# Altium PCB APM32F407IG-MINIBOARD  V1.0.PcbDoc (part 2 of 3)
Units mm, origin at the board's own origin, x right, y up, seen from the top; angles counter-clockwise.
Board outline 442.79 x 366.46 mm, 2 copper layers (Top Layer, Bottom Layer); 220 components, 190 nets, 1232 pads, 648 vias.
Unrouted connection lines stored in the file: 190.
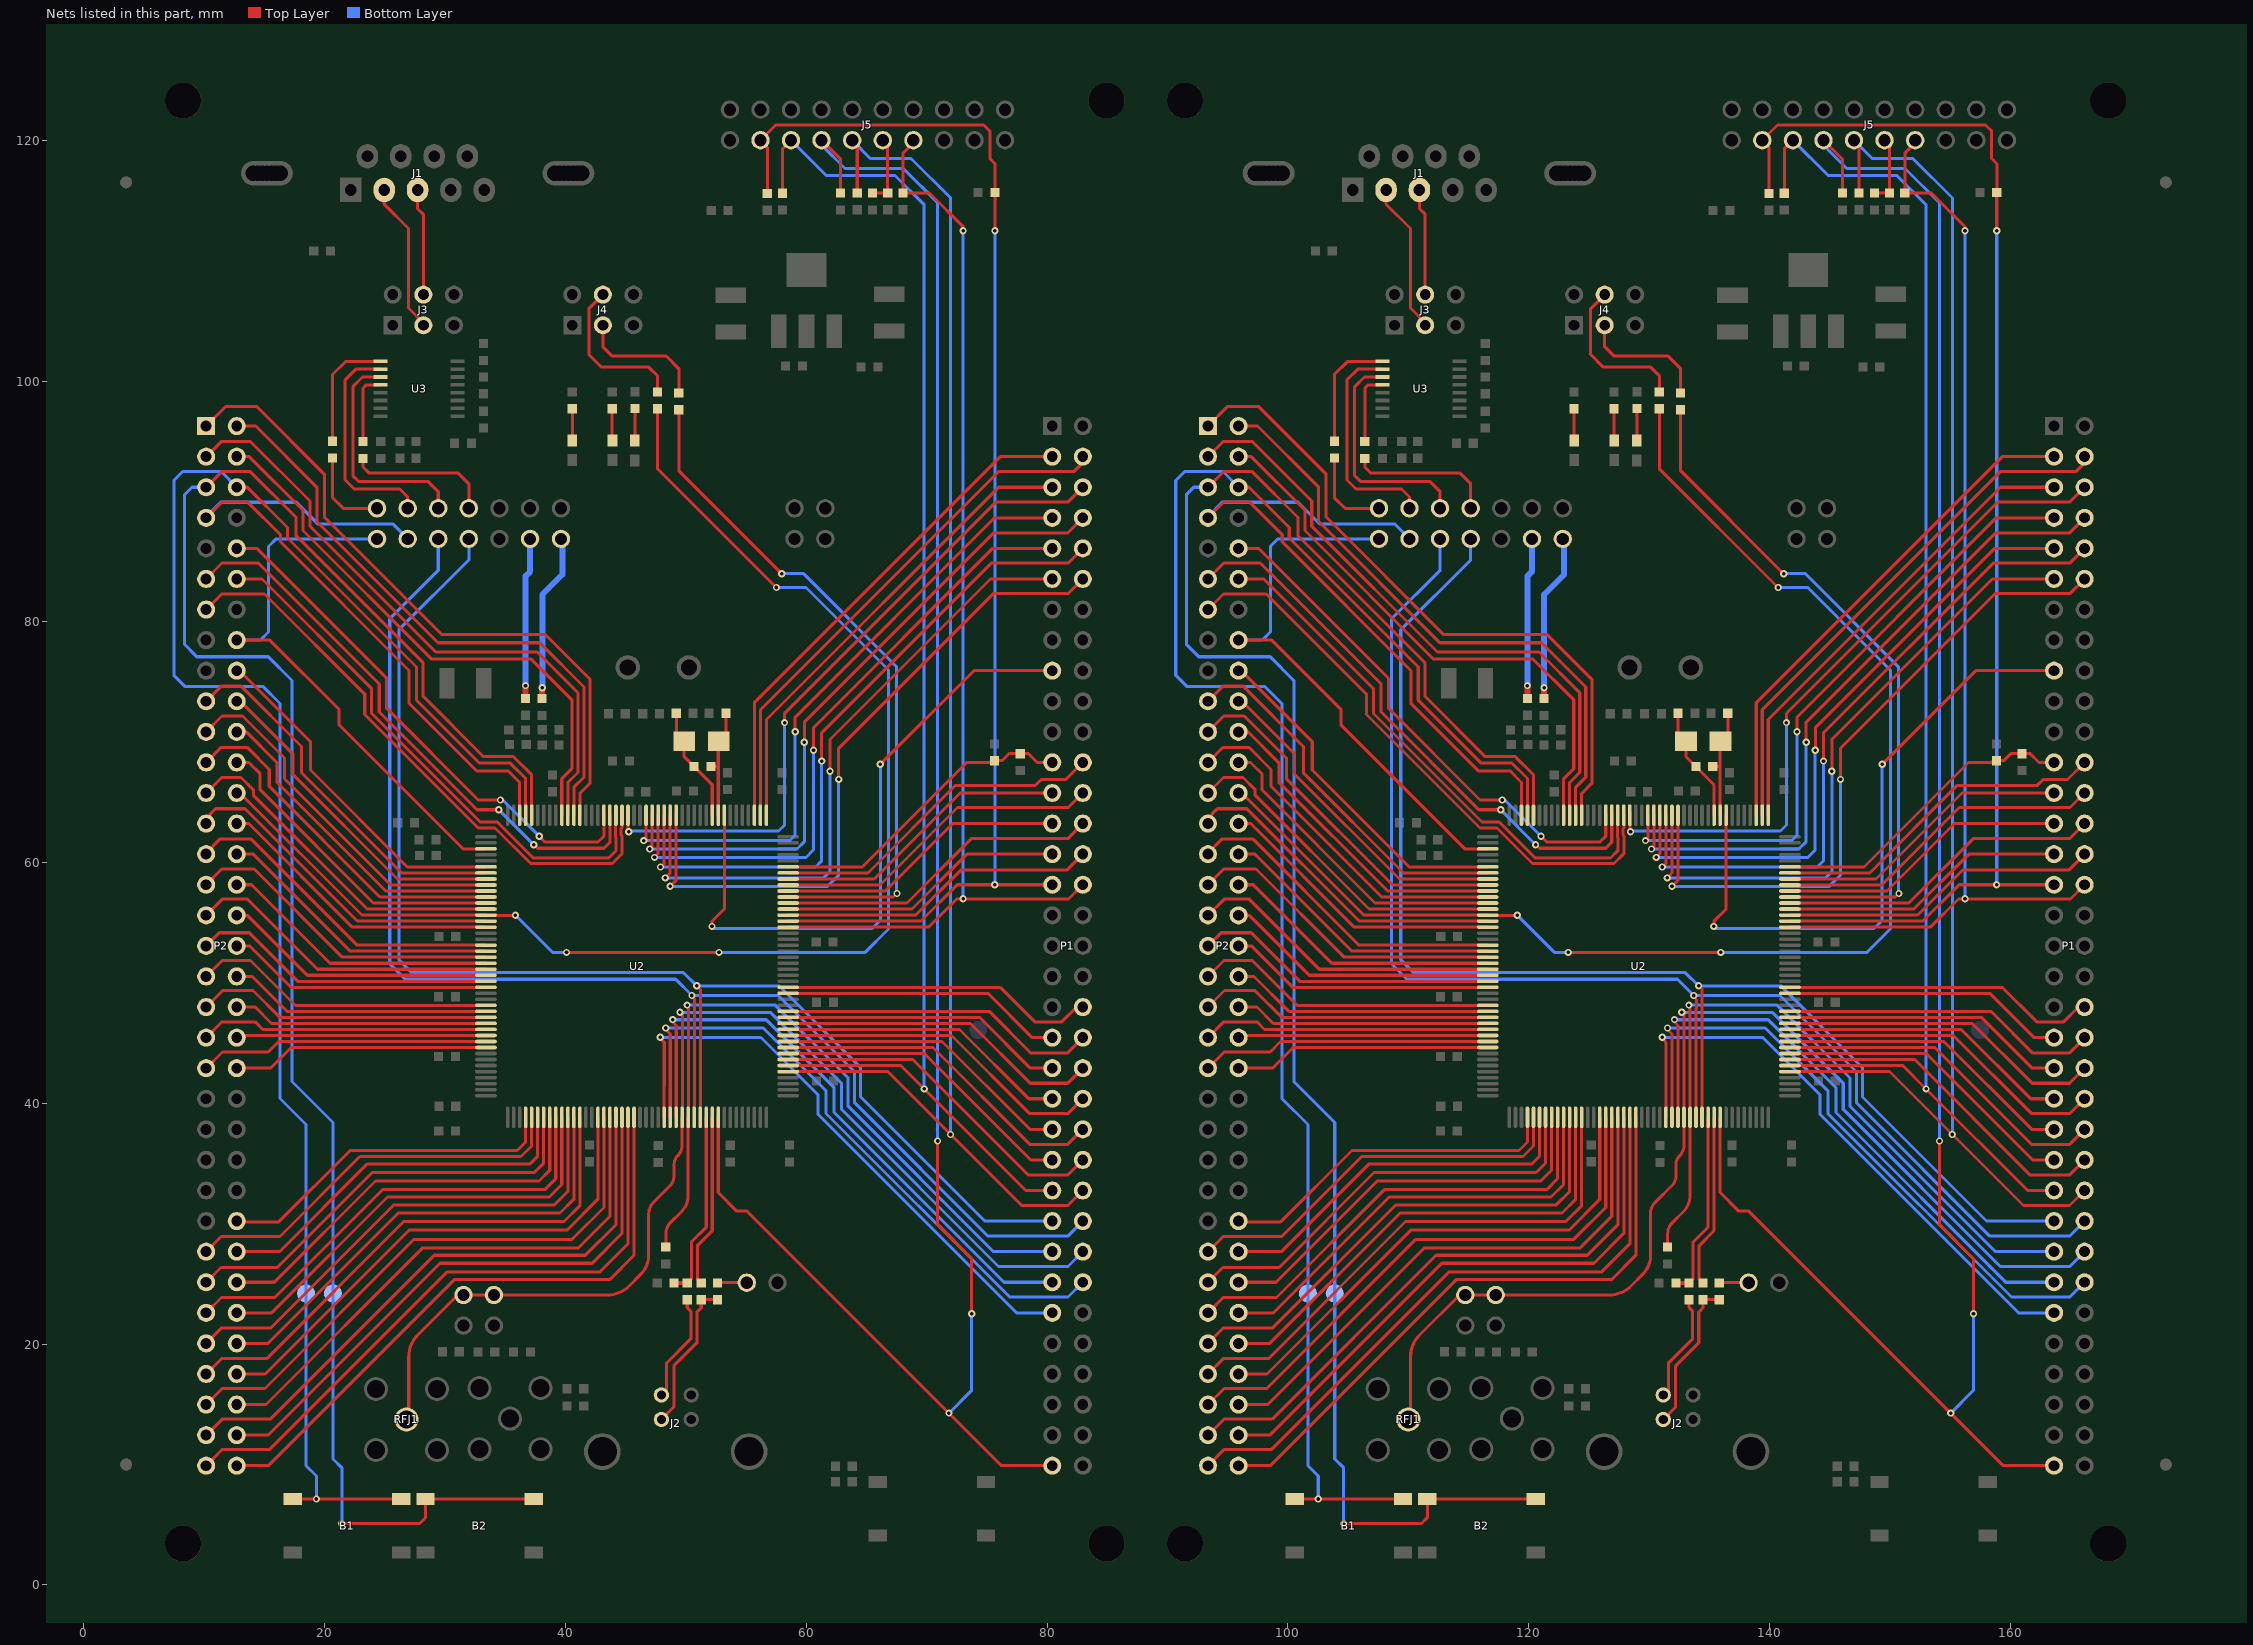
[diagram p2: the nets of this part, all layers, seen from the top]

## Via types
v1: diameter 0.6, hole 0.3, Top Layer to Bottom Layer, 648 vias

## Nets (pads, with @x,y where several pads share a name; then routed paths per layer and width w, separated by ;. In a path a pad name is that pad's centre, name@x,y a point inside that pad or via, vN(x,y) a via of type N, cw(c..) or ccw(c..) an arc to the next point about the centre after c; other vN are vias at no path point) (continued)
NetJ2_2: J2.2 R2.1 | length 18.1
  Top Layer w0.254: J2.2@47.962,15.774 48.39,16.202 48.39,18.412 50.414,20.436 50.414,22.724 50.114,23.024 R2.1@50.114,23.689 ; J2.2@131.182,15.774 131.61,16.202 131.61,18.412 133.634,20.436 133.634,22.724 133.334,23.024 R2.1@133.334,23.689
NetJ2_3: J2.3 R1.1 R4.1 | length 25.3
  Top Layer w0.254: J2.3@47.962,13.742 49,14.78 49,18.192 50.914,20.106 50.914,22.656 51.273,23.015 R1.1@51.273,23.689 R4.1@52.614,23.689 ; J2.3@131.182,13.742 132.22,14.78 132.22,18.192 134.134,20.106 134.134,22.656 134.493,23.015 R1.1@134.493,23.689 R4.1@135.834,23.689
NetJ4_3: J4.3 R6.2 | length 21.8
  Top Layer w0.254: J4.3@43.103,104.637 43.103,102.837 43.85,102.09 48.35,102.09 49.41,101.03 R6.2@49.41,99.007 ; J4.3@126.323,104.637 126.323,102.837 127.07,102.09 131.57,102.09 132.63,101.03 R6.2@132.63,99.007
NetJ4_4: J4.4 R8.1 | length 26.5
  Top Layer w0.254: J4.4@43.103,107.177 41.94,106.014 41.94,102.2 42.99,101.15 46.92,101.15 47.64,100.43 R8.1@47.64,99.095 ; J4.4@126.323,107.177 125.16,106.014 125.16,102.2 126.21,101.15 130.14,101.15 130.86,100.43 R8.1@130.86,99.095
NetJ5_11: J5.11 R24.2 R25.1 | length 11.6
  Top Layer w0.254: R24.2@65.514,115.613 65.524,115.623 R25.1@66.764,115.623 66.764,119.595 J5.11@66.354,120.005 ; R24.2@148.734,115.613 148.744,115.623 R25.1@149.984,115.623 149.984,119.595 J5.11@149.574,120.005
NetJ7_2: J7.2 L2.2 | length 28.2
  Top Layer w0.5: L2.2@38.06,73.627 38.06,74.52 v1(38.07,74.53) ; L2.2@121.28,73.627 121.28,74.52 v1(121.29,74.53)
  Bottom Layer w0.5: v1(38.07,74.53) 38.07,82.27 39.73,83.93 39.73,86.78 J7.2@39.62,86.89 ; J7.2@39.13,86.89 J7.2@39.13,86.97 ; v1(121.29,74.53) 121.29,82.27 122.95,83.93 122.95,86.78 J7.2@122.84,86.89 ; J7.2@122.35,86.89 J7.2@122.35,86.97
NetJ8_2: J8.2 L1.2 | length 26.8
  Top Layer w0.5: v1(36.68,74.7) 36.688,74.692 L1.2@36.688,73.637 ; v1(119.9,74.7) 119.908,74.692 L1.2@119.908,73.637
  Bottom Layer w0.5: v1(36.68,74.7) 36.68,83.79 37.06,84.17 J8.2@37.06,86.89 ; v1(119.9,74.7) 119.9,83.79 120.28,84.17 J8.2@120.28,86.89
NetJ10_2: J10.2 R4.2 | length 4.9
  Top Layer w0.254: R4.2@52.614,25.086 R4.2@52.62,25.08 ; R4.2@52.614,25.105 J10.2@55.06,25.105 ; R4.2@135.834,25.086 R4.2@135.84,25.08 ; R4.2@135.834,25.105 J10.2@138.28,25.105
NetJ11_1: J11.1 U3.11 | length 38.1
  Top Layer w0.254: U3.11@24.635,100.334 23.144,100.334 22.33,99.52 22.33,92.14 22.8,91.67 28.56,91.67 29.43,90.8 J11.1@29.43,89.43 ; U3.11@107.855,100.334 106.364,100.334 105.55,99.52 105.55,92.14 106.02,91.67 111.78,91.67 112.65,90.8 J11.1@112.65,89.43
NetJ12_1: J12.1 R27.1 | length 24.2
  Top Layer w0.254: R27.1@23.174,93.576 23.174,92.855 23.65,92.38 31.05,92.38 31.97,91.46 J12.1@31.97,89.43 ; R27.1@106.394,93.576 106.394,92.855 106.87,92.38 114.27,92.38 115.19,91.46 J12.1@115.19,89.43
NetJ13_1: J13.1 U3.10 | length 36.7
  Top Layer w0.254: U3.10@24.635,100.984 22.584,100.984 21.7,100.1 21.7,91.78 22.44,91.04 26.22,91.04 26.89,90.37 J13.1@26.89,89.43 ; U3.10@107.855,100.984 105.804,100.984 104.92,100.1 104.92,91.78 105.66,91.04 109.44,91.04 110.11,90.37 J13.1@110.11,89.43
NetJ14_1: J14.1 R28.1 | length 14.7
  Top Layer w0.254: R28.1@20.65,93.601 20.65,90.31 21.53,89.43 J14.1@24.35,89.43 ; R28.1@103.87,93.601 103.87,90.31 104.75,89.43 J14.1@107.57,89.43
NetLED1_1: LED1.1 R7.1 | length 5.2
  Top Layer w0.254: LED1.1@40.563,95.073 R7.1@40.563,97.698 ; LED1.1@123.783,95.073 R7.1@123.783,97.698
NetLED2_1: LED2.1 R12.2 | length 5.3
  Top Layer w0.254: R12.2@43.877,97.703 43.877,95.091 LED2.1@43.907,95.061 ; R12.2@127.097,97.703 127.097,95.091 LED2.1@127.127,95.061
NetLED3_1: LED3.1 R11.2 | length 5.6
  Top Layer w0.254: LED3.1@45.76,94.901 45.78,94.921 R11.2@45.78,97.713 ; LED3.1@128.98,94.901 129,94.921 R11.2@129,97.713
NetR6_1: R6.1 U2.166 | length 115.9
  Top Layer w0.254: R6.1@49.41,97.61 49.41,92.55 57.96,84 v1(57.97,84) ; U2.166@58.49,57.14 67.25,57.14 v1(67.54,57.43) ; R6.1@132.63,97.61 132.63,92.55 141.18,84 v1(141.19,84) ; U2.166@141.71,57.14 150.47,57.14 v1(150.76,57.43)
  Bottom Layer w0.254: v1(57.97,84) 59.78,84 67.5,76.28 67.5,57.47 v1(67.54,57.43) ; v1(141.19,84) 143,84 150.72,76.28 150.72,57.47 v1(150.76,57.43)
NetR27_2: R27.2 U3.12 | length 12
  Top Layer w0.254: R27.2@23.174,94.973 23.174,99.414 23.444,99.684 U3.12@24.635,99.684 ; R27.2@106.394,94.973 106.394,99.414 106.664,99.684 U3.12@107.855,99.684
NetR28_2: R28.2 U3.9 | length 20
  Top Layer w0.254: R28.2@20.65,94.998 20.65,100.54 21.72,101.611 24.612,101.611 U3.9@24.635,101.634 U3.9@24.658,101.611 ; R28.2@103.87,94.998 103.87,100.54 104.94,101.611 107.832,101.611 U3.9@107.855,101.634 U3.9@107.878,101.611
PA0: B2.2 B2.3 P2.5 TP5.1 U2.40 | length 316
  Top Layer w0.254: P2.5@10.15,91.181 11.439,92.47 13.82,92.47 17.63,88.66 17.63,87.14 28.17,76.6 28.17,73.81 33.18,68.8 35.676,68.8 37.19,67.286 U2.40@37.19,63.94 ; v1(21.42,5.098) 27.88,5.098 28.37,5.588 B2.2@28.37,7.145 B2.3@37.37,7.145 ; P2.5@93.37,91.181 94.659,92.47 97.04,92.47 100.85,88.66 100.85,87.14 111.39,76.6 111.39,73.81 116.4,68.8 118.896,68.8 120.41,67.286 U2.40@120.41,63.94 ; v1(104.64,5.098) 111.1,5.098 111.59,5.588 B2.2@111.59,7.145 B2.3@120.59,7.145
  Bottom Layer w0.254: P2.5@10.15,91.181 8.971,91.181 8.35,90.56 8.35,78.13 9.38,77.1 15.31,77.1 17.28,75.13 17.28,41.81 20.68,38.41 TP5.1@20.68,24.21 20.68,10.458 21.42,9.718 v1(21.42,5.098) ; P2.5@93.37,91.181 92.191,91.181 91.57,90.56 91.57,78.13 92.6,77.1 98.53,77.1 100.5,75.13 100.5,41.81 103.9,38.41 TP5.1@103.9,24.21 103.9,10.458 104.64,9.718 v1(104.64,5.098)
PA1: B1.2 B1.3 P2.6 TP6.1 U2.41 | length 295.1
  Top Layer w0.254: P2.6@12.69,91.181 13.559,91.181 16.9,87.84 16.9,86.97 27.617,76.253 27.617,73.493 32.85,68.26 35.41,68.26 36.69,66.98 U2.41@36.69,63.94 ; B1.2@17.35,7.145 B1.3@26.35,7.145 ; P2.6@95.91,91.181 96.779,91.181 100.12,87.84 100.12,86.97 110.837,76.253 110.837,73.493 116.07,68.26 118.63,68.26 119.91,66.98 U2.41@119.91,63.94 ; B1.2@100.57,7.145 B1.3@109.57,7.145
  Bottom Layer w0.254: P2.6@12.69,91.181 11.391,92.48 8.21,92.48 7.47,91.74 7.47,75.55 8.38,74.64 14.85,74.64 16.28,73.21 16.28,40.41 18.45,38.24 TP6.1@18.45,24.21 18.45,9.908 19.31,9.048 v1(19.31,7.138) ; P2.6@95.91,91.181 94.611,92.48 91.43,92.48 90.69,91.74 90.69,75.55 91.6,74.64 98.07,74.64 99.5,73.21 99.5,40.41 101.67,38.24 TP6.1@101.67,24.21 101.67,9.908 102.53,9.048 v1(102.53,7.138)
PA2: J13.2 P2.7 U2.42 | length 119
  Top Layer w0.254: P2.7@10.15,88.641 11.479,89.97 13.57,89.97 16.32,87.22 16.32,86.64 27,75.96 27,73.23 32.61,67.62 35.23,67.62 36.19,66.66 U2.42@36.19,63.94 ; P2.7@93.37,88.641 94.699,89.97 96.79,89.97 99.54,87.22 99.54,86.64 110.22,75.96 110.22,73.23 115.83,67.62 118.45,67.62 119.41,66.66 U2.42@119.41,63.94
  Bottom Layer w0.254: P2.7@10.15,88.641 10.15,88.74 11.34,89.93 17.63,89.93 19.42,88.14 25.64,88.14 J13.2@26.89,86.89 ; P2.7@93.37,88.641 93.37,88.74 94.56,89.93 100.85,89.93 102.64,88.14 108.86,88.14 J13.2@110.11,86.89
PA3: J14.2 P2.16 U2.47 | length 97.5
  Top Layer w0.254: 13.53,78.481 P2.16@12.69,78.481 15.439,78.481 21.18,72.74 21.18,71.45 31.49,61.14 U2.47@33.39,61.14 ; 96.75,78.481 P2.16@95.91,78.481 98.659,78.481 104.4,72.74 104.4,71.45 114.71,61.14 U2.47@116.61,61.14
  Bottom Layer w0.254: P2.16@12.69,78.481 14.651,78.481 15.33,79.16 15.33,86.25 15.97,86.89 J14.2@24.35,86.89 ; P2.16@95.91,78.481 97.871,78.481 98.55,79.16 98.55,86.25 99.19,86.89 J14.2@107.57,86.89
PA4: P2.18 U2.50 | length 57.7
  Top Layer w0.254: P2.18@12.69,75.941 12.919,75.941 18.81,70.05 18.81,67.69 26.86,59.64 U2.50@33.39,59.64 ; P2.18@95.91,75.941 96.139,75.941 102.03,70.05 102.03,67.69 110.08,59.64 U2.50@116.61,59.64
PA5: P2.19 U2.51 | length 62.9
  Top Layer w0.254: P2.19@10.15,73.401 11.399,74.65 13.07,74.65 18.07,69.65 18.07,67.46 26.39,59.14 U2.51@33.39,59.14 ; P2.19@93.37,73.401 94.619,74.65 96.29,74.65 101.29,69.65 101.29,67.46 109.61,59.14 U2.51@116.61,59.14
PA6: P2.20 U2.52 | length 55.6
  Top Layer w0.254: P2.20@12.69,73.401 12.969,73.401 17.34,69.03 17.34,67.35 26.05,58.64 U2.52@33.39,58.64 ; P2.20@95.91,73.401 96.189,73.401 100.56,69.03 100.56,67.35 109.27,58.64 U2.52@116.61,58.64
PA7: P2.21 U2.53 | length 61.2
  Top Layer w0.254: P2.21@10.15,70.861 11.459,72.17 13.17,72.17 16.66,68.68 16.66,66.97 25.49,58.14 U2.53@33.39,58.14 ; P2.21@93.37,70.861 94.679,72.17 96.39,72.17 99.88,68.68 99.88,66.97 108.71,58.14 U2.53@116.61,58.14
PA8: P1.55 R15.1 U2.119 | length 121.9
  Top Layer w0.254: R15.1@48.333,28.057 48.333,29.169 cw(c49.621,29.169) 48.709,30.079 ; 48.71,30.08 49.645,31.015 ccw(c48.329,32.331) 50.19,32.331 U2.119@50.19,38.84 50.2,38.85 50.2,48.06 v1(50.1,48.16) ; R15.1@131.552,28.057 131.552,29.169 cw(c132.841,29.169) 131.929,30.079 ; 131.93,30.08 132.865,31.015 ; 132.866,31.016 ccw(c131.549,32.331) 133.41,32.331 U2.119@133.41,38.84 133.42,38.85 133.42,48.06 v1(133.32,48.16)
  Bottom Layer w0.254: v1(50.1,48.16) 57.43,48.16 63.48,42.11 63.48,39.76 75.559,27.681 P1.55@80.431,27.681 ; v1(133.32,48.16) 140.65,48.16 146.7,42.11 146.7,39.76 158.779,27.681 P1.55@163.651,27.681
PA9: J11.2 P1.54 U2.120 | length 232.3
  Top Layer w0.254: v1(50.5,48.96) 50.5,48.86 50.727,48.633 50.727,47.9 50.7,47.873 50.7,38.85 U2.120@50.69,38.84 ; v1(133.72,48.96) 133.72,48.86 133.947,48.633 133.947,47.9 133.92,47.873 133.92,38.85 U2.120@133.91,38.84
  Bottom Layer w0.254: J11.2@29.43,86.89 29.43,84.28 25.4,80.25 25.4,51.59 26.68,50.31 49.15,50.31 v1(50.5,48.96) 57.67,48.96 64.02,42.61 64.02,40.05 75.1,28.97 81.72,28.97 P1.54@82.971,30.221 ; J11.2@112.65,86.89 112.65,84.28 108.62,80.25 108.62,51.59 109.9,50.31 132.37,50.31 v1(133.72,48.96) 140.89,48.96 147.24,42.61 147.24,40.05 158.32,28.97 164.94,28.97 P1.54@166.191,30.221
PA10: J12.2 P1.53 U2.121 | length 226.2
  Top Layer w0.254: v1(50.9,49.76) 51.2,49.46 51.2,38.85 U2.121@51.19,38.84 ; v1(134.12,49.76) 134.42,49.46 134.42,38.85 U2.121@134.41,38.84
  Bottom Layer w0.254: J12.2@31.97,86.89 31.97,85.14 26.16,79.33 26.16,51.94 27.24,50.86 49.8,50.86 v1(50.9,49.76) 57.73,49.76 64.52,42.97 64.52,40.52 74.819,30.221 P1.53@80.431,30.221 ; J12.2@115.19,86.89 115.19,85.14 109.38,79.33 109.38,51.94 110.46,50.86 133.02,50.86 v1(134.12,49.76) 140.95,49.76 147.74,42.97 147.74,40.52 158.039,30.221 P1.53@163.651,30.221
PA11: R2.2 R16.2 U2.122 | length 31
  Top Layer w0.254: R2.2@50.114,25.086 50.448,25.42 50.448,28.478 51.69,29.72 U2.122@51.69,38.84 ; R2.2@133.334,25.086 133.668,25.42 133.668,28.478 134.91,29.72 U2.122@134.91,38.84
  Top Layer w0.3: R16.2@49.015,25.075 50.104,25.075 R2.2@50.114,25.086 ; R16.2@132.235,25.075 133.324,25.075 R2.2@133.334,25.086
PA12: R1.2 U2.123 | length 28.8
  Top Layer w0.254: R1.2@51.273,25.086 50.948,25.411 50.948,28.178 52.19,29.42 U2.123@52.19,38.84 ; R1.2@134.493,25.086 134.168,25.411 134.168,28.178 135.41,29.42 U2.123@135.41,38.84
PA13: J5.7 P1.69 R21.1 U2.124 | length 325.9
  Top Layer w0.254: U2.124@52.69,38.84 52.69,32.59 54.23,31.05 55.07,31.05 v1(71.85,14.27) 76.219,9.901 P1.69@80.431,9.901 ; J5.7@61.274,120.005 62.854,118.425 R21.1@62.854,115.613 ; v1(70.91,36.87) 70.91,29.95 73.74,27.12 v1(73.74,22.53) ; U2.124@135.91,38.84 135.91,32.59 137.45,31.05 138.29,31.05 v1(155.07,14.27) 159.439,9.901 P1.69@163.651,9.901 ; J5.7@144.494,120.005 146.074,118.425 R21.1@146.074,115.613 ; v1(154.13,36.87) 154.13,29.95 156.96,27.12 v1(156.96,22.53)
  Bottom Layer w0.254: J5.7@61.274,120.005 61.274,119.595 63.214,117.655 68.054,117.655 70.91,114.799 v1(70.91,36.87) ; v1(71.85,14.27) 73.74,16.16 v1(73.74,22.53) ; J5.7@144.494,120.005 144.494,119.595 146.434,117.655 151.274,117.655 154.13,114.799 v1(154.13,36.87) ; v1(155.07,14.27) 156.96,16.16 v1(156.96,22.53)
PA14: J5.9 P1.52 R22.2 U2.137 | length 244.3
  Top Layer w0.254: U2.137@58.49,42.64 66.76,42.64 77.89,31.51 81.72,31.51 P1.52@82.971,32.761 ; J5.9@63.814,120.005 64.234,119.585 R22.2@64.234,115.623 ; U2.137@141.71,42.64 149.98,42.64 161.11,31.51 164.94,31.51 P1.52@166.191,32.761 ; J5.9@147.034,120.005 147.454,119.585 R22.2@147.454,115.623
  Bottom Layer w0.254: J5.9@63.814,120.005 65.324,118.495 68.704,118.495 71.99,115.209 71.99,37.42 v1(71.98,37.41) ; J5.9@147.034,120.005 148.544,118.495 151.924,118.495 155.21,115.209 155.21,37.42 v1(155.2,37.41)
PA15: J5.5 P1.51 R20.1 U2.138 | length 235.3
  Top Layer w0.254: R20.1@58.024,115.603 58.024,119.295 J5.5@58.734,120.005 ; U2.138@58.49,43.14 67.86,43.14 v1(69.8,41.2) 78.239,32.761 P1.51@80.431,32.761 ; R20.1@141.244,115.603 141.244,119.295 J5.5@141.954,120.005 ; U2.138@141.71,43.14 151.08,43.14 v1(153.02,41.2) 161.459,32.761 P1.51@163.651,32.761
  Bottom Layer w0.254: J5.5@58.734,120.005 61.664,117.075 67.364,117.075 69.79,114.649 69.79,41.21 v1(69.8,41.2) ; J5.5@141.954,120.005 144.884,117.075 150.584,117.075 153.01,114.649 153.01,41.21 v1(153.02,41.2)
PB0: P2.24 U2.56 | length 52.6
  Top Layer w0.254: P2.24@12.69,68.321 13.679,68.321 14.63,67.37 14.63,66.04 24.03,56.64 U2.56@33.39,56.64 ; P2.24@95.91,68.321 96.899,68.321 97.85,67.37 97.85,66.04 107.25,56.64 U2.56@116.61,56.64
PB1: P2.25 U2.57 | length 57.1
  Top Layer w0.254: P2.25@10.15,65.781 11.439,67.07 13.05,67.07 14.07,66.05 14.07,65.6 23.53,56.14 U2.57@33.39,56.14 ; P2.25@93.37,65.781 94.659,67.07 96.27,67.07 97.29,66.05 97.29,65.6 106.75,56.14 U2.57@116.61,56.14
PB2: P2.26 R8.2 U2.58 | length 226.2
  Top Layer w0.254: P2.26@12.69,65.781 12.949,65.781 23.09,55.64 U2.58@33.39,55.64 ; U2.58@33.39,55.62 v1(35.84,55.62) ; v1(40.08,52.54) v1(52.75,52.54) ; R8.2@47.64,97.698 47.64,92.71 57.5,82.85 v1(57.52,82.85) ; P2.26@95.91,65.781 96.169,65.781 106.31,55.64 U2.58@116.61,55.64 ; U2.58@116.61,55.62 v1(119.06,55.62) ; v1(123.3,52.54) v1(135.97,52.54) ; R8.2@130.86,97.698 130.86,92.71 140.72,82.85 v1(140.74,82.85)
  Bottom Layer w0.254: v1@35.89,55.67 v1(35.84,55.62) 38.92,52.54 v1(40.08,52.54) ; v1(52.75,52.54) 64.89,52.54 66.83,54.48 66.83,75.99 59.97,82.85 v1(57.52,82.85) ; v1@119.11,55.67 v1(119.06,55.62) 122.14,52.54 v1(123.3,52.54) ; v1(135.97,52.54) 148.11,52.54 150.05,54.48 150.05,75.99 143.19,82.85 v1(140.74,82.85)
PB3: J5.13 P1.32 R23.1 U2.161 | length 185.3
  Top Layer w0.254: U2.161@58.49,54.64 70.15,54.64 72.49,56.98 81.79,56.98 P1.32@82.971,58.161 ; J5.13@68.894,120.005 68.894,119.795 68.034,118.935 R23.1@68.034,115.623 70.236,115.623 73.03,112.83 v1(73.03,112.482) ; U2.161@141.71,54.64 153.37,54.64 155.71,56.98 165.01,56.98 P1.32@166.191,58.161 ; J5.13@152.114,120.005 152.114,119.795 151.254,118.935 R23.1@151.254,115.623 153.456,115.623 156.25,112.83 v1(156.25,112.482)
  Bottom Layer w0.254: v1(73.03,56.99) v1(73.03,112.482) ; v1(156.25,56.99) v1(156.25,112.482)
PB4: J5.3 P1.31 R19.1 R26.2 U2.162 | length 220.9
  Top Layer w0.254: J5.3@56.171,119.982 57.464,121.275 74.736,121.275 75.244,120.767 75.244,118.481 75.689,118.036 R26.2@75.689,115.685 ; J5.3@56.194,120.005 56.194,119.959 56.764,119.389 R19.1@56.764,115.583 ; U2.162@58.49,55.14 69.53,55.14 72.551,58.161 P1.31@80.431,58.161 ; v1(75.669,112.482) R26.2@75.669,115.655 ; J5.3@139.391,119.982 140.684,121.275 157.956,121.275 158.464,120.767 158.464,118.481 158.909,118.036 R26.2@158.909,115.685 ; J5.3@139.414,120.005 139.414,119.959 139.984,119.389 R19.1@139.984,115.583 ; U2.162@141.71,55.14 152.75,55.14 155.771,58.161 P1.31@163.651,58.161 ; v1(158.889,112.482) R26.2@158.889,115.655
  Bottom Layer w0.254: v1(75.66,58.159) 75.669,58.15 v1(75.669,112.482) ; v1(158.88,58.159) 158.889,58.15 v1(158.889,112.482)
PB5: P1.30 U2.163 | length 53.2
  Top Layer w0.254: U2.163@58.49,55.64 69.1,55.64 72.83,59.37 81.64,59.37 P1.30@82.971,60.701 ; U2.163@141.71,55.64 152.32,55.64 156.05,59.37 164.86,59.37 P1.30@166.191,60.701
PB6: P1.29 U2.164 | length 47.7
  Top Layer w0.254: U2.164@58.49,56.14 68.78,56.14 73.341,60.701 P1.29@80.431,60.701 ; U2.164@141.71,56.14 152,56.14 156.561,60.701 P1.29@163.651,60.701
PB7: P1.28 U2.165 | length 54.4
  Top Layer w0.254: U2.165@58.49,56.64 68.36,56.64 73.71,61.99 81.72,61.99 P1.28@82.971,63.241 ; U2.165@141.71,56.64 151.58,56.64 156.93,61.99 164.94,61.99 P1.28@166.191,63.241
PB8: P1.27 U2.167 | length 48.9
  Top Layer w0.254: U2.167@58.49,57.64 66.56,57.64 72.161,63.241 P1.27@80.431,63.241 P1.27@80.311,63.36 ; U2.167@141.71,57.64 149.78,57.64 155.381,63.241 P1.27@163.651,63.241 P1.27@163.531,63.36
PB9: P1.26 U2.168 | length 55.3
  Top Layer w0.254: U2.168@58.49,58.14 66.13,58.14 72.56,64.57 81.76,64.57 P1.26@82.971,65.781 ; U2.168@141.71,58.14 149.35,58.14 155.78,64.57 164.98,64.57 P1.26@166.191,65.781
PB10: P2.43 U2.79 | length 48.3
  Top Layer w0.254: P2.43@10.15,42.921 11.499,44.27 15.31,44.27 16.18,45.14 U2.79@33.39,45.14 ; P2.43@93.37,42.921 94.719,44.27 98.53,44.27 99.4,45.14 U2.79@116.61,45.14
PB11: P2.44 U2.80 | length 42.8
  Top Layer w0.254: P2.44@12.69,42.921 15.501,42.921 17.22,44.64 U2.80@33.39,44.64 ; P2.44@95.91,42.921 98.721,42.921 100.44,44.64 U2.80@116.61,44.64
PB12: P2.54 U2.92 | length 57.6
  Top Layer w0.254: P2.54@12.69,30.221 12.751,30.16 16.19,30.16 22.11,36.08 35.98,36.08 36.69,36.79 U2.92@36.69,38.84 ; P2.54@95.91,30.221 95.971,30.16 99.41,30.16 105.33,36.08 119.2,36.08 119.91,36.79 U2.92@119.91,38.84
PB13: P2.55 U2.93 | length 66.1
  Top Layer w0.254: P2.55@10.15,27.681 11.414,28.945 16.285,28.945 22.92,35.58 36.31,35.58 37.19,36.46 U2.93@37.19,38.84 ; P2.55@93.37,27.681 94.634,28.945 99.505,28.945 106.14,35.58 119.53,35.58 120.41,36.46 U2.93@120.41,38.84
PB14: P2.56 U2.94 | length 63
  Top Layer w0.254: P2.56@12.69,27.681 16.241,27.681 23.54,34.98 37.06,34.98 37.69,35.61 U2.94@37.69,38.84 ; P2.56@95.91,27.681 99.461,27.681 106.76,34.98 120.28,34.98 120.91,35.61 U2.94@120.91,38.84
PB15: P2.57 U2.95 | length 71.9
  Top Layer w0.254: P2.57@10.15,25.141 11.379,26.37 16.06,26.37 23.94,34.25 37.41,34.25 38.19,35.03 U2.95@38.19,38.84 ; P2.57@93.37,25.141 94.599,26.37 99.28,26.37 107.16,34.25 120.63,34.25 121.41,35.03 U2.95@121.41,38.84
PC0: P2.1 U2.32 | length 111.3
  Top Layer w0.254: P2.1@10.15,96.261 11.759,97.87 14.37,97.87 19.969,92.271 19.969,88.701 29.74,78.93 38.34,78.93 42.03,75.24 42.03,66.58 41.19,65.74 U2.32@41.19,63.94 ; P2.1@93.37,96.261 94.979,97.87 97.59,97.87 103.189,92.271 103.189,88.701 112.96,78.93 121.56,78.93 125.25,75.24 125.25,66.58 124.41,65.74 U2.32@124.41,63.94
PC1: P2.2 U2.33 | length 101
  Top Layer w0.254: P2.2@12.69,96.261 14.259,96.261 19.34,91.18 19.34,88.33 29.41,78.26 37.85,78.26 41.53,74.58 41.53,67.09 40.69,66.25 U2.33@40.69,63.94 ; P2.2@95.91,96.261 97.479,96.261 102.56,91.18 102.56,88.33 112.63,78.26 121.07,78.26 124.75,74.58 124.75,67.09 123.91,66.25 U2.33@123.91,63.94
PC2: P2.3 U2.34 | length 103.6
  Top Layer w0.254: P2.3@10.15,93.721 11.399,94.97 13.84,94.97 18.77,90.04 18.77,87.94 29.22,77.49 37.64,77.49 41.03,74.1 41.03,67.49 40.19,66.65 U2.34@40.19,63.94 ; P2.3@93.37,93.721 94.619,94.97 97.06,94.97 101.99,90.04 101.99,87.94 112.44,77.49 120.86,77.49 124.25,74.1 124.25,67.49 123.41,66.65 U2.34@123.41,63.94
PC3: P2.4 U2.35 | length 94.2
  Top Layer w0.254: P2.4@12.69,93.721 13.739,93.721 18.2,89.26 18.2,87.59 28.89,76.9 37.15,76.9 40.53,73.52 40.53,67.8 39.69,66.96 U2.35@39.69,63.94 ; P2.4@95.91,93.721 96.959,93.721 101.42,89.26 101.42,87.59 112.11,76.9 120.37,76.9 123.75,73.52 123.75,67.8 122.91,66.96 U2.35@122.91,63.94
PC4: P2.22 U2.54 | length 54.3
  Top Layer w0.254: P2.22@12.69,70.861 13.479,70.861 16.04,68.3 16.04,66.67 25.07,57.64 U2.54@33.39,57.64 ; P2.22@95.91,70.861 96.699,70.861 99.26,68.3 99.26,66.67 108.29,57.64 U2.54@116.61,57.64
PC5: P2.23 U2.55 | length 59.5
  Top Layer w0.254: P2.23@10.15,68.321 11.399,69.57 13.56,69.57 15.39,67.74 15.39,66.33 24.58,57.14 U2.55@33.39,57.14 ; P2.23@93.37,68.321 94.619,69.57 96.78,69.57 98.61,67.74 98.61,66.33 107.8,57.14 U2.55@116.61,57.14
PC6: P1.59 U2.115 | length 99.7
  Top Layer w0.254: v1@47.8,45.464 48.2,45.064 48.2,41.5 48.19,41.49 U2.115@48.19,38.84 ; v1@131.02,45.464 131.42,45.064 131.42,41.5 131.41,41.49 U2.115@131.41,38.84
  Bottom Layer w0.254: v1@47.8,45.464 56.236,45.464 60.98,40.72 60.98,39.09 77.469,22.601 P1.59@80.431,22.601 ; v1@131.02,45.464 139.456,45.464 144.2,40.72 144.2,39.09 160.689,22.601 P1.59@163.651,22.601
  other v1: 47.876,45.5 131.096,45.5
PC7: P1.58 U2.116 | length 106.1
  Top Layer w0.254: v1@48.26,46.2 48.7,45.76 48.7,38.85 U2.116@48.69,38.84 ; v1@131.48,46.2 131.92,45.76 131.92,38.85 U2.116@131.91,38.84
  Bottom Layer w0.254: v1(48.32,46.26) 56.43,46.26 61.64,41.05 61.64,39.16 76.89,23.91 81.74,23.91 P1.58@82.971,25.141 ; v1(131.54,46.26) 139.65,46.26 144.86,41.05 144.86,39.16 160.11,23.91 164.96,23.91 P1.58@166.191,25.141
PC8: P1.57 U2.117 | length 100
  Top Layer w0.254: v1(48.9,46.96) 48.9,46.76 49.2,46.46 49.2,38.85 U2.117@49.19,38.84 ; v1(132.12,46.96) 132.12,46.76 132.42,46.46 132.42,38.85 U2.117@132.41,38.84
  Bottom Layer w0.254: v1(48.9,46.96) 48.917,46.943 56.678,46.943 62.32,41.301 62.32,39.24 76.419,25.141 P1.57@80.431,25.141 ; v1(132.12,46.96) 132.137,46.943 139.898,46.943 145.54,41.301 145.54,39.24 159.639,25.141 P1.57@163.651,25.141
PC9: P1.56 PJ1.2 PJ2.2 RFJ1.5 U2.118 | length 188.8
  Top Layer w0.254: RFJ1.5@26.98,14.03 26.98,18.958 cw(c29.52,18.958) 27.724,20.754 31.05,24.08 PJ2.2@31.52,24.08 PJ1.2@34.05,24.08 43.488,24.08 ccw(c43.488,26.62) 45.284,24.824 46.26,25.8 ; 46.261,25.801 ccw(c44.691,27.369) 46.91,27.369 46.91,30.817 cw(c48.276,30.817) 47.309,31.782 48.742,33.214 ccw(c47.698,34.042) 49.03,34.042 49.03,34.965 cw(c49.935,34.965) 49.294,35.604 ccw(c48.341,36.559) 49.69,36.559 U2.118@49.69,38.84 49.7,38.85 49.7,47.36 49.5,47.56 v1(49.5,47.57) ; RFJ1.5@110.2,14.03 110.2,18.958 cw(c112.74,18.958) 110.944,20.754 ; 110.944,20.754 114.27,24.08 PJ2.2@114.74,24.08 PJ1.2@117.27,24.08 126.708,24.08 ccw(c126.708,26.62) 128.504,24.824 129.48,25.8 ; 129.481,25.801 ccw(c127.911,27.369) 130.13,27.369 130.13,30.817 cw(c131.496,30.817) 130.529,31.782 ; 130.53,31.782 131.962,33.214 ccw(c130.918,34.042) 132.25,34.042 132.25,34.965 cw(c133.155,34.965) 132.514,35.604 ; 132.515,35.605 ccw(c131.561,36.559) 132.91,36.559 U2.118@132.91,38.84 132.92,38.85 132.92,47.36 132.72,47.56 v1(132.72,47.57)
  Bottom Layer w0.254: v1(49.5,47.57) 49.537,47.533 57.057,47.533 62.92,41.67 62.92,39.5 75.97,26.45 81.74,26.45 P1.56@82.971,27.681 ; v1(132.72,47.57) 132.757,47.533 140.277,47.533 146.14,41.67 146.14,39.5 159.19,26.45 164.96,26.45 P1.56@166.191,27.681
PC10: P1.50 U2.139 | length 58
  Top Layer w0.254: U2.139@58.49,43.64 68.85,43.64 78.46,34.03 81.7,34.03 P1.50@82.971,35.301 ; U2.139@141.71,43.64 152.07,43.64 161.68,34.03 164.92,34.03 P1.50@166.191,35.301
PC11: P1.49 U2.140 | length 51.2
  Top Layer w0.254: U2.140@58.49,44.14 69.81,44.14 78.649,35.301 P1.49@80.431,35.301 ; U2.140@141.71,44.14 153.03,44.14 161.869,35.301 P1.49@163.651,35.301
PC12: P1.48 U2.141 | length 56.6
  Top Layer w0.254: U2.141@58.49,44.64 70.52,44.64 78.56,36.6 81.73,36.6 P1.48@82.971,37.841 ; U2.141@141.71,44.64 153.74,44.64 161.78,36.6 164.95,36.6 P1.48@166.191,37.841
PC13: P1.17 U2.8 | length 108.9
  Top Layer w0.254: v1(52.17,54.7) 52.17,55.12 53.19,56.14 U2.8@53.19,63.94 ; v1(66.15,68.16) 73.931,75.941 P1.17@80.431,75.941 ; v1(135.39,54.7) 135.39,55.12 136.41,56.14 U2.8@136.41,63.94 ; v1(149.37,68.16) 157.151,75.941 P1.17@163.651,75.941
  Bottom Layer w0.254: v1(52.17,54.7) 52.347,54.523 65.473,54.523 66.15,55.2 v1(66.15,68.16) ; v1(135.39,54.7) 135.567,54.523 148.693,54.523 149.37,55.2 v1(149.37,68.16)
PC14: C14.2 R13.1 U2.9 Y1.2 | length 18.7
  Top Layer w0.254: R13.1@52.078,67.97 52.68,67.97 52.69,67.96 ; U2.9@52.69,63.94 52.69,67.96 ; C14.2@53.328,72.41 53.328,70.692 Y1.2@52.716,70.08 52.69,70.054 52.69,67.96 ; R13.1@135.298,67.97 135.9,67.97 135.91,67.96 ; U2.9@135.91,63.94 135.91,67.96 ; C14.2@136.548,72.41 136.548,70.692 Y1.2@135.936,70.08 135.91,70.054 135.91,67.96
PC15: C13.2 R13.2 U2.10 Y1.1 | length 19.4
  Top Layer w0.254: C13.2@49.202,72.4 49.202,70.729 Y1.1@49.851,70.08 49.851,68.801 R13.2@50.682,67.97 52.19,66.461 U2.10@52.19,63.94 ; C13.2@132.421,72.4 132.421,70.729 Y1.1@133.071,70.08 133.071,68.801 R13.2@133.901,67.97 135.41,66.462 U2.10@135.41,63.94
PC_RX: J1.3 J3.4 | length 19.4
  Top Layer w0.254: J1.3@27.141,115.303 J1.3@27.713,115.875 27.713,114.322 28.191,113.844 J3.4@28.191,107.177 ; J1.3@110.361,115.303 J1.3@110.933,115.875 110.933,114.322 111.411,113.844 J3.4@111.411,107.177
PC_TX: J1.2 J3.3 | length 25.2
  Top Layer w0.254: J1.2@24.944,115.875 24.944,114.691 26.964,112.67 26.964,106.075 28.191,104.848 J3.3@28.191,104.637 ; J1.2@108.164,115.875 108.164,114.691 110.184,112.67 110.184,106.075 111.411,104.848 J3.3@111.411,104.637
PD0: P1.47 U2.142 | length 49.9
  Top Layer w0.254: U2.142@58.49,45.14 71.28,45.14 78.579,37.841 P1.47@80.431,37.841 ; U2.142@141.71,45.14 154.5,45.14 161.799,37.841 P1.47@163.651,37.841
PD1: P1.46 U2.143 | length 55.3
  Top Layer w0.254: U2.143@58.49,45.64 72.06,45.64 78.53,39.17 81.76,39.17 P1.46@82.971,40.381 ; U2.143@141.71,45.64 155.28,45.64 161.75,39.17 164.98,39.17 P1.46@166.191,40.381
PD2: P1.45 U2.144 | length 48.7
  Top Layer w0.254: U2.144@58.49,46.14 72.73,46.14 78.489,40.381 P1.45@80.431,40.381 ; U2.144@141.71,46.14 155.95,46.14 161.709,40.381 P1.45@163.651,40.381
PD3: P1.44 U2.145 | length 54.1
  Top Layer w0.254: U2.145@58.49,46.64 73.64,46.64 78.61,41.67 81.72,41.67 P1.44@82.971,42.921 ; U2.145@141.71,46.64 156.86,46.64 161.83,41.67 164.94,41.67 P1.44@166.191,42.921
PD4: P1.43 U2.146 | length 47.4
  Top Layer w0.254: U2.146@58.49,47.14 74.39,47.14 78.609,42.921 P1.43@80.431,42.921 ; U2.146@141.71,47.14 157.61,47.14 161.829,42.921 P1.43@163.651,42.921
PD5: P1.42 U2.147 | length 52.9
  Top Layer w0.254: U2.147@58.49,47.64 75.2,47.64 78.67,44.17 81.68,44.17 P1.42@82.971,45.461 ; U2.147@141.71,47.64 158.42,47.64 161.89,44.17 164.9,44.17 P1.42@166.191,45.461
PD6: P1.41 U2.150 | length 46.9
  Top Layer w0.254: U2.150@58.49,49.14 75.1,49.14 78.779,45.461 P1.41@80.431,45.461 ; U2.150@141.71,49.14 158.32,49.14 161.999,45.461 P1.41@163.651,45.461
PD7: P1.40 U2.151 | length 52.4
  Top Layer w0.254: U2.151@58.49,49.64 76.11,49.64 78.98,46.77 81.23,46.77 82.461,48.001 P1.40@82.971,48.001 ; U2.151@141.71,49.64 159.33,49.64 162.2,46.77 164.45,46.77 165.681,48.001 P1.40@166.191,48.001
PD8: P2.58 U2.96 | length 68.5
  Top Layer w0.254: P2.58@12.69,25.141 15.801,25.141 24.21,33.55 37.8,33.55 38.69,34.44 U2.96@38.69,38.84 ; P2.58@95.91,25.141 99.021,25.141 107.43,33.55 121.02,33.55 121.91,34.44 U2.96@121.91,38.84
PD9: P2.59 U2.97 | length 77.2
  Top Layer w0.254: P2.59@10.249,22.7 11.419,23.87 15.84,23.87 24.8,32.83 38.28,32.83 39.19,33.74 U2.97@39.19,38.84 ; P2.59@93.469,22.7 94.639,23.87 99.06,23.87 108.02,32.83 121.5,32.83 122.41,33.74 U2.97@122.41,38.84
PD10: P2.60 U2.98 | length 74
  Top Layer w0.254: P2.60@12.69,22.601 15.591,22.601 25.21,32.22 38.65,32.22 39.69,33.26 U2.98@39.69,38.84 ; P2.60@95.91,22.601 98.811,22.601 108.43,32.22 121.87,32.22 122.91,33.26 U2.98@122.91,38.84
PD11: P2.61 U2.99 | length 82.9
  Top Layer w0.254: P2.61@10.15,20.061 11.439,21.35 15.54,21.35 25.76,31.57 39.08,31.57 40.19,32.68 U2.99@40.19,38.84 ; P2.61@93.37,20.061 94.659,21.35 98.76,21.35 108.98,31.57 122.3,31.57 123.41,32.68 U2.99@123.41,38.84
PD12: P2.62 U2.100 | length 79.5
  Top Layer w0.254: P2.62@12.69,20.061 15.281,20.061 26.11,30.89 39.55,30.89 40.69,32.03 U2.100@40.69,38.84 ; P2.62@95.91,20.061 98.501,20.061 109.33,30.89 122.77,30.89 123.91,32.03 U2.100@123.91,38.84
PD13: P2.63 U2.101 | length 88.3
  Top Layer w0.254: P2.63@10.15,17.521 11.419,18.79 15.17,18.79 26.56,30.18 39.874,30.18 41.19,31.496 U2.101@41.19,38.84 ; P2.63@93.37,17.521 94.639,18.79 98.39,18.79 109.78,30.18 123.094,30.18 124.41,31.496 U2.101@124.41,38.84
PD14: P2.64 U2.104 | length 85.6
  Top Layer w0.254: P2.64@12.69,17.521 15.051,17.521 27,29.47 40.13,29.47 42.69,32.03 U2.104@42.69,38.84 ; P2.64@95.91,17.521 98.271,17.521 110.22,29.47 123.35,29.47 125.91,32.03 U2.104@125.91,38.84
PD15: P2.65 U2.105 | length 94.6
  Top Layer w0.254: P2.65@10.15,14.981 11.489,16.32 15.04,16.32 27.42,28.7 40.54,28.7 43.19,31.35 U2.105@43.19,38.84 ; P2.65@93.37,14.981 94.709,16.32 98.26,16.32 110.64,28.7 123.76,28.7 126.41,31.35 U2.105@126.41,38.84
PDR_ON: P1.23 R9.2 R10.1 U2.171 | length 52.2
  Top Layer w0.254: U2.171@58.49,59.64 64.64,59.64 73.321,68.321 R10.1@75.35,68.321 ; R10.1@75.35,68.463 R10.1@75.64,68.463 76.252,68.463 76.836,69.047 78.453,69.047 79.179,68.321 P1.23@80.431,68.321 ; U2.171@141.71,59.64 147.86,59.64 156.541,68.321 R10.1@158.57,68.321 ; R10.1@158.57,68.463 R10.1@158.86,68.463 159.472,68.463 160.056,69.047 161.673,69.047 162.399,68.321 P1.23@163.651,68.321
PE0: P1.25 U2.169 | length 49.8
  Top Layer w0.254: U2.169@58.49,58.64 65.64,58.64 72.781,65.781 P1.25@80.431,65.781 ; U2.169@141.71,58.64 148.86,58.64 156.001,65.781 P1.25@163.651,65.781
PE1: P1.24 U2.170 | length 56.6
  Top Layer w0.254: U2.170@58.49,59.14 65.12,59.14 72.4,66.42 79.04,66.42 79.52,66.9 81.55,66.9 P1.24@82.971,68.321 ; U2.170@141.71,59.14 148.34,59.14 155.62,66.42 162.26,66.42 162.74,66.9 164.77,66.9 P1.24@166.191,68.321
PE2: P1.5 U2.1 | length 79.4
  Top Layer w0.254: U2.1@56.69,63.94 56.69,71.89 75.981,91.181 P1.5@80.431,91.181 ; U2.1@139.91,63.94 139.91,71.89 159.201,91.181 P1.5@163.651,91.181
PE3: P1.4 U2.2 | length 89.1
  Top Layer w0.254: U2.2@56.19,63.94 56.19,72.69 75.97,92.47 82.23,92.47 82.971,93.211 P1.4@82.971,93.721 ; U2.2@139.41,63.94 139.41,72.69 159.19,92.47 165.45,92.47 166.191,93.211 P1.4@166.191,93.721
PE4: P1.3 U2.3 | length 85.1
  Top Layer w0.254: U2.3@55.69,63.94 55.69,73.29 76.121,93.721 P1.3@80.431,93.721 ; U2.3@138.91,63.94 138.91,73.29 159.341,93.721 P1.3@163.651,93.721
PE7: P2.34 U2.68 | length 46
  Top Layer w0.254: P2.34@12.851,55.46 P2.34@12.69,55.621 13.569,55.621 18.55,50.64 U2.68@33.39,50.64 ; P2.34@96.071,55.46 P2.34@95.91,55.621 96.789,55.621 101.77,50.64 U2.68@116.61,50.64
PE8: P2.35 U2.69 | length 50.7
  Top Layer w0.254: P2.35@10.15,53.081 11.239,54.17 13.74,54.17 17.77,50.14 U2.69@33.39,50.14 ; P2.35@93.37,53.081 94.459,54.17 96.96,54.17 100.99,50.14 U2.69@116.61,50.14
PE9: P2.36 U2.70 | length 44.3
  Top Layer w0.254: P2.36@12.69,53.081 13.749,53.081 17.19,49.64 U2.70@33.39,49.64 ; P2.36@95.91,53.081 96.969,53.081 100.41,49.64 U2.70@116.61,49.64
PE10: P2.37 U2.73 | length 50.7
  Top Layer w0.254: P2.37@10.15,50.541 11.479,51.87 13.83,51.87 17.564,48.136 33.386,48.136 U2.73@33.39,48.14 ; P2.37@93.37,50.541 94.699,51.87 97.05,51.87 100.784,48.136 116.606,48.136 U2.73@116.61,48.14
PE11: P2.38 U2.74 | length 43.8
  Top Layer w0.254: P2.38@12.69,50.541 13.969,50.541 16.87,47.64 U2.74@33.39,47.64 ; P2.38@95.91,50.541 97.189,50.541 100.09,47.64 U2.74@116.61,47.64
PE12: P2.39 U2.75 | length 49.5
  Top Layer w0.254: P2.39@10.15,48.001 11.519,49.37 14.04,49.37 16.27,47.14 U2.75@33.39,47.14 ; P2.39@93.37,48.001 94.739,49.37 97.26,49.37 99.49,47.14 U2.75@116.61,47.14
PE13: P2.40 U2.76 | length 42.5
  Top Layer w0.254: P2.40@12.69,48.001 14.219,48.001 15.58,46.64 U2.76@33.39,46.64 ; P2.40@95.91,48.001 97.439,48.001 98.8,46.64 U2.76@116.61,46.64
PE14: P2.41 U2.77 | length 48.1
  Top Layer w0.254: P2.41@10.15,45.461 11.459,46.77 14.22,46.77 14.85,46.14 U2.77@33.39,46.14 ; P2.41@93.37,45.461 94.679,46.77 97.44,46.77 98.07,46.14 U2.77@116.61,46.14
PE15: P2.42 U2.78 | length 41.5
  Top Layer w0.254: P2.42@12.69,45.461 12.869,45.64 U2.78@33.39,45.64 ; P2.42@95.91,45.461 96.089,45.64 U2.78@116.61,45.64
PF0: P1.12 U2.16 | length 114.3
  Top Layer w0.254: v1(48.69,58.03) 49.19,58.53 U2.16@49.19,63.94 ; v1(62.69,66.91) 62.69,69.49 75.57,82.37 81.78,82.37 P1.12@82.971,83.561 ; v1(131.91,58.03) 132.41,58.53 U2.16@132.41,63.94 ; v1(145.91,66.91) 145.91,69.49 158.79,82.37 165,82.37 P1.12@166.191,83.561
  Bottom Layer w0.254: v1(48.69,58.03) 61.76,58.03 62.69,58.96 v1(62.69,66.91) ; v1(131.91,58.03) 144.98,58.03 145.91,58.96 v1(145.91,66.91)
PF1: P1.11 U2.17 | length 108.5
  Top Layer w0.254: v1(48.29,58.73) 48.69,59.13 U2.17@48.69,63.94 ; v1(61.97,67.59) 61.97,70.23 75.301,83.561 P1.11@80.431,83.561 ; v1(131.51,58.73) 131.91,59.13 U2.17@131.91,63.94 ; v1(145.19,67.59) 145.19,70.23 158.521,83.561 P1.11@163.651,83.561
  Bottom Layer w0.254: v1(48.29,58.73) 61.46,58.73 61.97,59.24 v1(61.97,67.59) ; v1(131.51,58.73) 144.68,58.73 145.19,59.24 v1(145.19,67.59)
PF2: P1.10 U2.18 | length 113.4
  Top Layer w0.254: v1(47.89,59.63) 48.19,59.93 U2.18@48.19,63.94 ; v1(61.28,68.43) 61.28,70.78 75.37,84.87 81.74,84.87 P1.10@82.971,86.101 ; v1(131.11,59.63) 131.41,59.93 U2.18@131.41,63.94 ; v1(144.5,68.43) 144.5,70.78 158.59,84.87 164.96,84.87 P1.10@166.191,86.101
  Bottom Layer w0.254: v1(47.89,59.63) 60.77,59.63 ; 60.77,59.63 61.28,60.14 v1(61.28,68.43) ; v1(131.11,59.63) 143.99,59.63 ; 143.99,59.63 144.5,60.14 v1(144.5,68.43)
PF3: P1.9 U2.19 | length 105.9
  Top Layer w0.254: v1(47.39,60.43) 47.69,60.73 U2.19@47.69,63.94 ; v1(60.6,69.33) 60.6,71.2 75.501,86.101 P1.9@80.431,86.101 ; v1(130.61,60.43) 130.91,60.73 U2.19@130.91,63.94 ; v1(143.82,69.33) 143.82,71.2 158.721,86.101 P1.9@163.651,86.101
  Bottom Layer w0.254: 47.69,60.43 59.97,60.43 60.59,61.05 60.59,69.33 v1(60.6,69.33) ; 130.91,60.43 143.19,60.43 143.81,61.05 143.81,69.33 v1(143.82,69.33)
PF4: P1.8 U2.20 | length 112.2
  Top Layer w0.254: v1(46.99,61.13) 47.19,61.33 U2.20@47.19,63.94 ; v1(59.84,69.99) 59.84,71.67 75.54,87.37 81.7,87.37 P1.8@82.971,88.641 ; v1(130.21,61.13) 130.41,61.33 U2.20@130.41,63.94 ; v1(143.06,69.99) 143.06,71.67 158.76,87.37 164.92,87.37 P1.8@166.191,88.641
  Bottom Layer w0.254: v1(46.99,61.13) 59.23,61.13 59.84,61.74 v1(59.84,69.99) ; v1(130.21,61.13) 142.45,61.13 143.06,61.74 v1(143.06,69.99)
PF5: P1.7 U2.21 | length 106
  Top Layer w0.254: v1(46.49,61.83) 46.69,62.03 U2.21@46.69,63.94 ; v1(59.08,70.86) 59.08,72.08 75.641,88.641 P1.7@80.431,88.641 ; v1(129.71,61.83) 129.91,62.03 U2.21@129.91,63.94 ; v1(142.3,70.86) 142.3,72.08 158.861,88.641 P1.7@163.651,88.641
  Bottom Layer w0.254: v1(46.49,61.83) 58.64,61.83 59.07,62.26 59.07,70.86 v1(59.08,70.86) ; v1(129.71,61.83) 141.86,61.83 142.29,62.26 142.29,70.86 v1(142.3,70.86)
PF6: P1.6 U2.24 | length 113.1
  Top Layer w0.254: U2.24@45.19,64.18 U2.24@45.19,63.94 45.19,62.62 v1(45.25,62.56) ; v1(58.2,71.63) 58.2,72.4 75.77,89.97 81.76,89.97 P1.6@82.971,91.181 ; U2.24@128.41,64.18 U2.24@128.41,63.94 128.41,62.62 v1(128.47,62.56) ; v1(141.42,71.63) 141.42,72.4 158.99,89.97 164.98,89.97 P1.6@166.191,91.181
  Bottom Layer w0.254: v1@45.35,62.62 57.7,62.62 58.2,63.12 v1(58.2,71.63) ; v1@128.57,62.62 140.92,62.62 141.42,63.12 v1(141.42,71.63)
PF7: P2.13 U2.25 | length 97.9
  Top Layer w0.254: P2.13@10.15,81.021 11.439,82.31 15,82.31 23.324,73.986 23.324,72.296 32.74,62.88 34.15,62.88 37.104,59.926 43.873,59.926 44.69,60.743 44.69,62.223 44.623,62.29 44.623,62.83 44.69,62.897 U2.25@44.69,63.94 ; P2.13@93.37,81.021 94.659,82.31 98.22,82.31 106.543,73.986 106.543,72.296 115.96,62.88 117.37,62.88 120.324,59.926 127.093,59.926 127.91,60.743 127.91,62.223 127.843,62.29 127.843,62.83 127.91,62.897 U2.25@127.91,63.94
PF8: P2.12 U2.26 | length 91.1
  Top Layer w0.254: P2.12@12.69,83.561 14.789,83.561 23.9,74.45 23.9,72.38 32.91,63.37 34.335,63.37 37.322,60.384 38.15,60.384 ; 38.15,60.38 43.59,60.38 44.19,60.98 44.19,62.081 44.159,62.112 44.159,62.984 44.167,62.992 44.167,63.917 U2.26@44.19,63.94 ; P2.12@95.91,83.561 98.009,83.561 107.12,74.45 107.12,72.38 116.13,63.37 117.555,63.37 120.542,60.384 121.37,60.384 ; 121.37,60.38 126.81,60.38 127.41,60.98 127.41,62.081 127.379,62.112 127.379,62.984 127.387,62.992 127.387,63.917 U2.26@127.41,63.94
PF9: P2.11 U2.27 | length 95.5
  Top Layer w0.254: P2.11@10.15,83.561 11.469,84.88 14.48,84.88 24.53,74.83 24.53,72.51 32.65,64.39 v1(34.46,64.39) ; v1(37.36,61.48) 37.38,61.48 37.39,61.49 37.69,61.19 43.19,61.19 43.69,61.69 U2.27@43.69,63.94 ; P2.11@93.37,83.561 94.689,84.88 97.7,84.88 107.75,74.83 107.75,72.51 115.87,64.39 v1(117.68,64.39) ; v1(120.58,61.48) 120.6,61.48 120.61,61.49 120.91,61.19 126.41,61.19 126.91,61.69 U2.27@126.91,63.94
  Bottom Layer w0.254: v1(34.46,64.39) 34.46,64.38 v1(37.36,61.48) ; v1(117.68,64.39) 117.68,64.38 v1(120.58,61.48)
PF10: P2.10 U2.28 | length 88
  Top Layer w0.254: P2.10@12.69,86.101 14.339,86.101 25.14,75.3 25.14,72.81 32.75,65.2 v1(34.59,65.2) ; v1(37.81,62.18) 38.28,61.71 42.7,61.71 43.19,62.2 U2.28@43.19,63.94 ; P2.10@95.91,86.101 97.559,86.101 108.36,75.3 108.36,72.81 115.97,65.2 v1(117.81,65.2) ; v1(121.03,62.18) 121.5,61.71 125.92,61.71 126.41,62.2 U2.28@126.41,63.94
  Bottom Layer w0.254: v1(34.59,65.2) 34.79,65.2 v1(37.81,62.18) ; v1(117.81,65.2) 118.01,65.2 v1(121.03,62.18)
PF11: P2.27 U2.59 | length 54.9
  Top Layer w0.254: P2.27@10.15,63.69 10.93,64.47 13.38,64.47 22.71,55.14 U2.59@33.39,55.14 ; P2.27@93.37,63.69 94.15,64.47 96.6,64.47 105.93,55.14 U2.59@116.61,55.14
PF12: P2.28 U2.60 | length 48.5
  Top Layer w0.254: P2.28@12.69,63.241 13.689,63.241 22.29,54.64 U2.60@33.39,54.64 ; P2.28@95.91,63.241 96.909,63.241 105.51,54.64 U2.60@116.61,54.64
PF13: P2.29 U2.63 | length 54.8
  Top Layer w0.254: P2.29@10.15,60.79 11.33,61.97 13.86,61.97 22.69,53.14 U2.63@33.39,53.14 ; P2.29@93.37,60.79 94.55,61.97 97.08,61.97 105.91,53.14 U2.63@116.61,53.14
PF14: P2.30 U2.64 | length 48.1
  Top Layer w0.254: P2.30@12.69,60.701 14.059,60.701 22.12,52.64 U2.64@33.39,52.64 ; P2.30@95.91,60.701 97.279,60.701 105.34,52.64 U2.64@116.61,52.64
PF15: P2.31 U2.65 | length 53.6
  Top Layer w0.254: P2.31@10.15,58.161 11.449,59.46 14.14,59.46 21.46,52.14 U2.65@33.39,52.14 ; P2.31@93.37,58.161 94.669,59.46 97.36,59.46 104.68,52.14 U2.65@116.61,52.14
PG0: P2.32 U2.66 | length 46.8
  Top Layer w0.254: P2.32@12.69,58.161 13.919,58.161 20.44,51.64 U2.66@33.39,51.64 ; P2.32@95.91,58.161 97.139,58.161 103.66,51.64 U2.66@116.61,51.64
PG1: P2.33 U2.67 | length 52.4
  Top Layer w0.254: P2.33@10.15,55.621 11.489,56.96 13.58,56.96 19.4,51.14 U2.67@33.39,51.14 ; P2.33@93.37,55.621 94.709,56.96 96.8,56.96 102.62,51.14 U2.67@116.61,51.14
PG2: P2.66 U2.106 | length 91.4
  Top Layer w0.254: P2.66@12.69,14.981 15.121,14.981 28.14,28 41.08,28 43.69,30.61 U2.106@43.69,38.84 ; P2.66@95.91,14.981 98.341,14.981 111.36,28 124.3,28 126.91,30.61 U2.106@126.91,38.84
PG3: P2.67 U2.107 | length 100.4
  Top Layer w0.254: P2.67@10.15,12.441 11.479,13.77 15.48,13.77 29.09,27.38 41.65,27.38 44.19,29.92 U2.107@44.19,38.84 ; P2.67@93.37,12.441 94.699,13.77 98.7,13.77 112.31,27.38 124.87,27.38 127.41,29.92 U2.107@127.41,38.84
PG4: P2.68 U2.108 | length 97.2
  Top Layer w0.254: P2.68@12.69,12.441 15.291,12.441 29.57,26.72 42.21,26.72 44.69,29.2 U2.108@44.69,38.84 ; P2.68@95.91,12.441 98.511,12.441 112.79,26.72 125.43,26.72 127.91,29.2 U2.108@127.91,38.84
PG5: P2.69 U2.109 | length 106.4
  Top Layer w0.254: P2.69@10.15,9.901 11.509,11.26 15.44,11.26 30.18,26 42.86,26 45.19,28.33 U2.109@45.19,38.84 ; P2.69@93.37,9.901 94.729,11.26 98.66,11.26 113.4,26 126.08,26 128.41,28.33 U2.109@128.41,38.84
PG6: P2.70 U2.110 | length 103.4
  Top Layer w0.254: P2.70@12.69,9.901 15.311,9.901 30.76,25.35 43.67,25.35 45.69,27.37 U2.110@45.69,38.84 ; P2.70@95.91,9.901 98.531,9.901 113.98,25.35 126.89,25.35 128.91,27.37 U2.110@128.91,38.84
